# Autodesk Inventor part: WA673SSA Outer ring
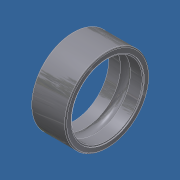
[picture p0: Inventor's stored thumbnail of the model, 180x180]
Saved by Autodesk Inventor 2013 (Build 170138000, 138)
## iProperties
Category: PARTsolutions
Created: 2011-07
Part Number: WA673SSA Outer ring
Catalog Web Link: www.cadenas.de
Description: Six types or - Metric system sizes
Document SubType Name: Modeling
Designer: PARTsolutions
Density: 1 g/cm^3
Material: Générique
NB: WA673SSA Outer ring
NN: Six types or
NT: Metric system sizes
NBSYN: $ORDER. Outer ring
LINA: WA673SSA Outer ring
SD: 3.0
D: 6
B: 2.0
R: 0.08
ORDER: WA673SSA
CR: 242
COR: 94
CRF: 25
CORF: 9,5
LSG: 60 000
LSO: 71 000
MASS: 0.20
D1: 7.2
D2: 7.2
C1: 0.6
C2: 0.6
ORDER1: 673
WSS: WA673SSA
WDS: SSA
UTWF: FL673
FORSS: FLWA673SA
FORDS: SSA
DA1: 3,6
DA2: 4,1
DA: 5,4
RAS: 0,08
MASS1: 0.26
B1: 2.5
VERS: 3
X: 1.500
N: 9
O: 14.130
RB: 0.444
KT: DUMMY
SUPPLIER: NTN
ARTICLENO: WA673SSA Outer ring
BOMINFO: WA673SSA Outer ring
CREATOR: CADENAS GmbH
PSOL_IDENT_0: {\\10.0.0.251\ps_data\23d-libs\ntn\ball_roller_bearings\miniature_extra_small_bb\metric_system_sizes
PSOL_IDENT_1: \mss_or.prj},189 {VTYP=3D},{NB=WA673SSA Outer ring},{LINA=WA673SSA Outer ring},{NN=Six types or},{DA
PSOL_IDENT_2: TE=11.12.2007 08:48:24},{GEOMDATE=02.04.2007 00:00:00},{VERSION=},{LINEID=12590},{LINESUBID=-1},{WBV
PSOL_IDENT_3: AR=}  {NB=WA673SSA Outer ring},{LINA=WA673SSA Outer ring},{KT=DUMMY},{IDNR=},{SD=3.0},{D=6},{B=2.0},
PSOL_IDENT_4: {R=0.08},{ORDER=WA673SSA},{CR=242},{COR=94},{CRF=25},{CORF=9,5},{LSG=60 000},{LSO=71 000},{MASS=0.20
PSOL_IDENT_5: },{D1=7.2},{D2=7.2},{C1=0.6},{C2=0.6},{ORDER1=673},{WSS=WA673SSA},{WDS=SSA},{UTWF=FL673},{FORSS=FLWA
PSOL_IDENT_6: 673SA},{FORDS=SSA},{DA1=3,6},{DA2=4,1},{DA=5,4},{RAS=0,08},{MASS1=0.26},{B1=2.5},{VERS=3},{X=1.5},{N
PSOL_IDENT_7: =9},{O=14.13},{RB=0.444}
Title: WA673SSA Outer ring
Author: Cadenas PARTsolutions
Comments: Metric system sizes
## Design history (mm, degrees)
sketch "Sketch_3"
  geometry: L1 (2.5, 0)-(0, 0); L2 (0, 2.92)-(0, 2.616); L3 (0, 2.616)-(0.056, 2.616); L4 (0.056, 2.616)-(0.056, 2.52); L5 (0.056, 2.52)-(0.898, 2.52); L6 (1.602, 2.52)-(2.444, 2.52); L7 (2.444, 2.52)-(2.444, 2.616); L8 (2.444, 2.616)-(2.5, 2.616); L9 (2.5, 2.616)-(2.5, 2.92); L10 (2.42, 3)-(0.08, 3); A1 r 0.444 centre (1.25, 2.25) between (1.602, 2.52) and (0.898, 2.52); A2 r 0.08 centre (2.42, 2.92) between (2.5, 2.92) and (2.42, 3); A3 r 0.08 centre (0.08, 2.92) between (0.08, 3) and (0, 2.92)
  constraints: 20 end point, 6 point on circle, 3 centre point
revolve "Revolution1" sketch "Sketch_3" stored, may be unused: angle "d0" = 360 deg
node "mss_or_XY"
node "mss_or_YZ"
node "mss_or_ZX"
node "mss_or_X"
node "mss_or_Y"
node "mss_or_Z"
node "mss_or_Center"
node "mss_or11_XY"
node "mss_or11_YZ"
node "mss_or11_ZX"
node "mss_or11_X"
node "mss_or11_Y"
node "mss_or11_Z"
node "mss_or11_Center"
node "mss_or2_9_XY"
node "mss_or2_9_YZ"
node "mss_or2_9_ZX"
node "mss_or2_9_X"
node "mss_or2_9_Y"
node "mss_or2_9_Z"
node "mss_or2_9_Center"
node "mss_or2_8_XY"
node "mss_or2_8_YZ"
node "mss_or2_8_ZX"
node "mss_or2_8_X"
node "mss_or2_8_Y"
node "mss_or2_8_Z"
node "mss_or2_8_Center"
node "mss_or2_1_XY"
node "mss_or2_1_YZ"
node "mss_or2_1_ZX"
node "mss_or2_1_X"
node "mss_or2_1_Y"
node "mss_or2_1_Z"
node "mss_or2_1_Center"
node "mss_or2_3_XY"
node "mss_or2_3_YZ"
node "mss_or2_3_ZX"
node "mss_or2_3_X"
node "mss_or2_3_Y"
node "mss_or2_3_Z"
node "mss_or2_3_Center"
node "mss_or2_2_XY"
node "mss_or2_2_YZ"
node "mss_or2_2_ZX"
node "mss_or2_2_X"
node "mss_or2_2_Y"
node "mss_or2_2_Z"
node "mss_or2_2_Center"
node "mss_or2_5_XY"
node "mss_or2_5_YZ"
node "mss_or2_5_ZX"
node "mss_or2_5_X"
node "mss_or2_5_Y"
node "mss_or2_5_Z"
node "mss_or2_5_Center"
node "mss_or2_4_XY"
node "mss_or2_4_YZ"
node "mss_or2_4_ZX"
node "mss_or2_4_X"
node "mss_or2_4_Y"
node "mss_or2_4_Z"
node "mss_or2_4_Center"
node "mss_or2_7_XY"
node "mss_or2_7_YZ"
node "mss_or2_7_ZX"
node "mss_or2_7_X"
node "mss_or2_7_Y"
node "mss_or2_7_Z"
node "mss_or2_7_Center"
node "mss_or2_6_XY"
node "mss_or2_6_YZ"
node "mss_or2_6_ZX"
node "mss_or2_6_X"
node "mss_or2_6_Y"
node "mss_or2_6_Z"
node "mss_or2_6_Center"
node "mss_or21_9_XY"
node "mss_or21_9_YZ"
node "mss_or21_9_ZX"
node "mss_or21_9_X"
node "mss_or21_9_Y"
node "mss_or21_9_Z"
node "mss_or21_9_Center"
node "mss_or21_8_XY"
node "mss_or21_8_YZ"
node "mss_or21_8_ZX"
node "mss_or21_8_X"
node "mss_or21_8_Y"
node "mss_or21_8_Z"
node "mss_or21_8_Center"
node "mss_or21_3_XY"
node "mss_or21_3_YZ"
node "mss_or21_3_ZX"
node "mss_or21_3_X"
node "mss_or21_3_Y"
node "mss_or21_3_Z"
node "mss_or21_3_Center"
node "mss_or21_2_XY"
node "mss_or21_2_YZ"
node "mss_or21_2_ZX"
node "mss_or21_2_X"
node "mss_or21_2_Y"
node "mss_or21_2_Z"
node "mss_or21_2_Center"
node "mss_or21_1_XY"
node "mss_or21_1_YZ"
node "mss_or21_1_ZX"
node "mss_or21_1_X"
node "mss_or21_1_Y"
node "mss_or21_1_Z"
node "mss_or21_1_Center"
node "mss_or21_7_XY"
node "mss_or21_7_YZ"
node "mss_or21_7_ZX"
node "mss_or21_7_X"
node "mss_or21_7_Y"
node "mss_or21_7_Z"
node "mss_or21_7_Center"
node "mss_or21_6_XY"
node "mss_or21_6_YZ"
node "mss_or21_6_ZX"
node "mss_or21_6_X"
node "mss_or21_6_Y"
node "mss_or21_6_Z"
node "mss_or21_6_Center"
node "mss_or21_5_XY"
node "mss_or21_5_YZ"
node "mss_or21_5_ZX"
node "mss_or21_5_X"
node "mss_or21_5_Y"
node "mss_or21_5_Z"
node "mss_or21_5_Center"
node "mss_or21_4_XY"
node "mss_or21_4_YZ"
node "mss_or21_4_ZX"
node "mss_or21_4_X"
node "mss_or21_4_Y"
node "mss_or21_4_Z"
node "mss_or21_4_Center"
node "Solide1"
node "Corps solides"
node "Corps surfaciques"
